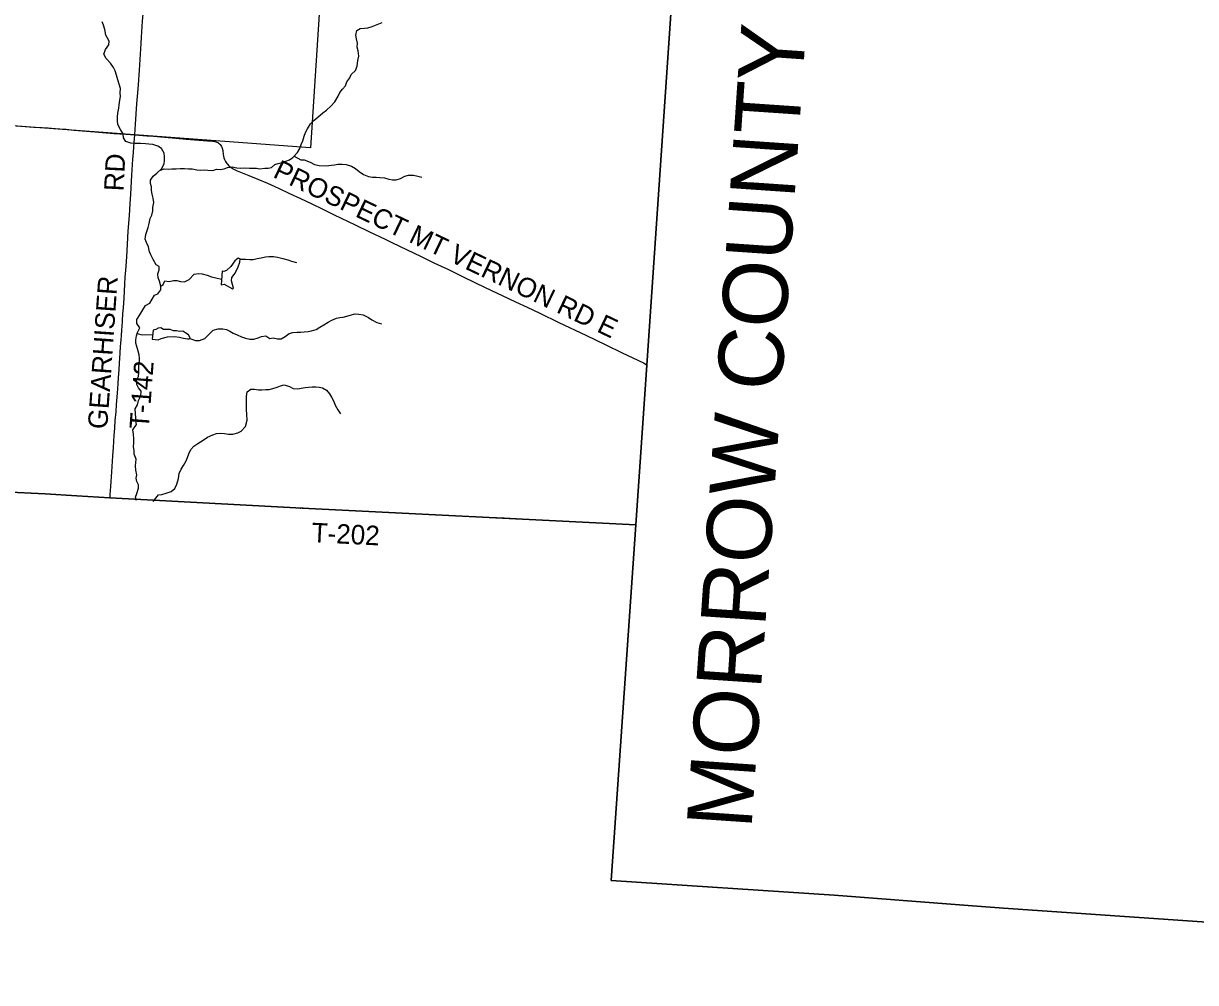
# Model space of a CAD drawing. Extents: x 1584893 to 1934202, y 663575 to 1091909.
# Drawn here: x 1814023 to 1832085, y 879859 to 894636 of the extents above; entities that cross this region are included whole.
import ezdxf

# ---------------------------------------------------------------- set-up
doc = ezdxf.new("R2010")
doc.units = 0
for name, color, linetype in [('GM_X_Adjacent_County', 7, 'Continuous'), ('GM_X_Adjacent_County_Text', 7, 'Continuous'), ('GM_X_County', 7, 'Continuous'), ('GM_X_Minor_Lake', 7, 'Continuous'), ('GM_X_Minor_River', 7, 'Continuous'), ('GM_X_Section', 7, 'Continuous'), ('GM_X_Township', 7, 'Continuous'), ('GM_X_Township_Road', 7, 'Continuous'), ('GM_X_Township_Road_Text', 7, 'Continuous')]:
    doc.layers.add(name, color=color, linetype=linetype)

msp = doc.modelspace()

# ---------------------------------------------------------------- linework, layer by layer
at = {"layer": 'GM_X_Adjacent_County'}
for points in [[(1850147, 879854), (1845959, 880135), (1842150, 880416), (1839410, 880574), (1836708, 880754), (1836682, 880495), (1835395, 880574), (1829123, 881005), (1828513, 881052), (1826517, 881205), (1823082, 881429), (1823458, 886911), (1823627, 889370), (1824025, 895167), (1824431, 901093), (1824723, 905333), (1827503, 905733)], [(1813717, 887422), (1814360, 887388), (1814847, 887358), (1815353, 887328), (1818316, 887169), (1823458, 886911), (1823082, 881429), (1826517, 881205), (1828513, 881052), (1829123, 881005), (1835395, 880574), (1836682, 880495), (1836708, 880754), (1839410, 880574), (1842150, 880416), (1845959, 880135), (1850147, 879854)]]:
    msp.add_lwpolyline(points, dxfattribs=at)
at = {"layer": 'GM_X_County'}
msp.add_lwpolyline([(1827503, 905733), (1824723, 905333), (1824431, 901093), (1824025, 895167), (1823627, 889370), (1823458, 886911), (1818316, 887169), (1815353, 887328), (1814847, 887358), (1814360, 887388), (1813717, 887422)], dxfattribs=at)
at = {"layer": 'GM_X_Minor_Lake'}
for points in [[(1817072, 890611), (1817118, 890622), (1817243, 890548), (1817259, 890558), (1817231, 890671), (1817236, 890721), (1817285, 890791), (1817332, 890886), (1817358, 890960), (1817364, 891010), (1817332, 891021), (1817282, 890979), (1817220, 890890), (1817151, 890829), (1817111, 890813), (1817083, 890820)], [(1817083, 890820), (1817072, 890611)], [(1816009, 889771), (1816097, 889760), (1816147, 889781), (1816244, 889810), (1816350, 889814), (1816426, 889805), (1816492, 889788), (1816550, 889775), (1816578, 889775), (1816594, 889793), (1816565, 889839), (1816527, 889866), (1816478, 889893), (1816430, 889891), (1816383, 889898), (1816333, 889903), (1816282, 889920), (1816231, 889920), (1816183, 889921), (1816142, 889948), (1816097, 889940), (1816063, 889921), (1816021, 889911)], [(1816021, 889911), (1816009, 889771)]]:
    msp.add_lwpolyline(points, dxfattribs=at)
at = {"layer": 'GM_X_Minor_River'}
for points in [[(1815476, 893078), (1815473, 893138), (1815474, 893200), (1815477, 893253), (1815494, 893329), (1815499, 893385), (1815506, 893455), (1815521, 893511), (1815516, 893569), (1815517, 893633), (1815499, 893700), (1815476, 893766), (1815457, 893841), (1815436, 893906), (1815409, 893958), (1815362, 894023), (1815297, 894096), (1815260, 894161), (1815289, 894233), (1815340, 894306), (1815343, 894366), (1815294, 894455), (1815275, 894542), (1815256, 894608), (1815237, 894661)], [(1816133, 892381), (1816136, 892378), (1816190, 892396), (1816258, 892393), (1816312, 892394), (1816378, 892399), (1816439, 892402), (1816503, 892403), (1816569, 892398), (1816625, 892394), (1816695, 892381), (1816759, 892376), (1816809, 892383), (1816865, 892376), (1816941, 892371), (1816996, 892392), (1817054, 892388), (1817114, 892395), (1817165, 892416), (1817241, 892429), (1817313, 892414), (1817373, 892407), (1817437, 892410), (1817507, 892407), (1817562, 892407), (1817614, 892408), (1817666, 892399), (1817742, 892408), (1817792, 892409), (1817844, 892415), (1817897, 892462), (1817950, 892477), (1818010, 892493), (1818068, 892512), (1818123, 892537), (1818173, 892569), (1818247, 892646), (1818280, 892708), (1818305, 892770), (1818326, 892827), (1818349, 892899), (1818372, 892955), (1818399, 893015), (1818448, 893089), (1818497, 893142), (1818558, 893191), (1818639, 893257), (1818694, 893300), (1818759, 893361), (1818824, 893431), (1818873, 893516), (1818898, 893570), (1818941, 893622), (1818988, 893677), (1819007, 893737), (1819052, 893797), (1819073, 893851), (1819140, 893910), (1819167, 893980), (1819174, 894064), (1819191, 894134), (1819180, 894212), (1819165, 894269), (1819170, 894331), (1819155, 894397), (1819144, 894458), (1819161, 894528), (1819214, 894561), (1819280, 894564), (1819332, 894570), (1819399, 894591), (1819473, 894618), (1819552, 894649)], [(1815764, 887284), (1815752, 887336), (1815769, 887394), (1815798, 887478), (1815797, 887528), (1815772, 887578), (1815762, 887629), (1815771, 887681), (1815756, 887755), (1815751, 887823), (1815761, 887924), (1815730, 888000), (1815731, 888053), (1815720, 888117), (1815722, 888171), (1815725, 888237), (1815720, 888308), (1815709, 888374), (1815763, 888456), (1815757, 888514), (1815756, 888564), (1815751, 888624), (1815746, 888697), (1815781, 888760), (1815794, 888828), (1815831, 888900), (1815836, 888972), (1815797, 889023), (1815770, 889074), (1815763, 889134), (1815794, 889198), (1815803, 889254), (1815801, 889304), (1815802, 889360), (1815811, 889426), (1815814, 889480), (1815805, 889531), (1815789, 889585), (1815768, 889660), (1815755, 889712), (1815756, 889764), (1815765, 889822), (1815782, 889876), (1815817, 889948), (1815770, 890015), (1815769, 890077), (1815818, 890145), (1815865, 890222), (1815902, 890290), (1815969, 890325), (1816008, 890387), (1816041, 890451), (1816093, 890472), (1816138, 890530), (1816139, 890590), (1816118, 890664), (1816097, 890717), (1816096, 890779), (1816117, 890841), (1816117, 890891), (1816066, 890918), (1816021, 891001), (1815988, 891070), (1815964, 891120), (1815952, 891193), (1815918, 891261), (1815899, 891314), (1815910, 891384), (1815944, 891492), (1815959, 891552), (1815976, 891630), (1816001, 891684), (1816016, 891748), (1816015, 891802), (1816030, 891876), (1816023, 891942), (1816006, 892005), (1815996, 892063), (1815997, 892117), (1815980, 892168), (1815981, 892224), (1816022, 892286), (1816077, 892331), (1816152, 892398), (1816193, 892472), (1816196, 892524), (1816195, 892588), (1816191, 892638), (1816148, 892711), (1816095, 892746), (1816017, 892769), (1815955, 892778), (1815903, 892783), (1815827, 892786), (1815747, 892787), (1815678, 892792), (1815601, 892819), (1815565, 892872), (1815562, 892936), (1815517, 893003), (1815476, 893078)], [(1818197, 892594), (1818299, 892537), (1818351, 892534), (1818439, 892501), (1818509, 892464), (1818581, 892447), (1818693, 892445), (1818763, 892452), (1818818, 892459), (1818870, 892467), (1818934, 892466), (1818998, 892461), (1819078, 892440), (1819141, 892401), (1819195, 892356), (1819264, 892308), (1819338, 892279), (1819400, 892268), (1819456, 892266), (1819516, 892263), (1819586, 892256), (1819656, 892235), (1819712, 892226), (1819768, 892227), (1819833, 892248), (1819902, 892285), (1819958, 892299), (1820034, 892298), (1820102, 892285), (1820162, 892270)], [(1817364, 891006), (1817443, 891005), (1817511, 891000), (1817565, 891002), (1817627, 891013), (1817687, 891024), (1817754, 891041), (1817804, 891048), (1817878, 891045), (1817936, 891038), (1818022, 891013), (1818098, 890992), (1818156, 890975), (1818232, 890952)], [(1816139, 890590), (1816174, 890614), (1816204, 890669), (1816268, 890660), (1816337, 890675), (1816387, 890675), (1816441, 890658), (1816507, 890655), (1816578, 890692), (1816655, 890771), (1816723, 890786), (1816775, 890778), (1816855, 890757), (1816919, 890734), (1816987, 890717), (1817076, 890697)], [(1816586, 889783), (1816676, 889751), (1816734, 889751), (1816817, 889784), (1816884, 889847), (1816949, 889910), (1817024, 889931), (1817098, 889930), (1817150, 889919), (1817201, 889893), (1817257, 889866), (1817317, 889841), (1817385, 889810), (1817447, 889787), (1817514, 889770), (1817571, 889771), (1817639, 889794), (1817692, 889815), (1817758, 889823), (1817821, 889784), (1817872, 889793), (1817938, 889778), (1817994, 889777), (1818056, 889812), (1818117, 889858), (1818174, 889873), (1818240, 889878), (1818290, 889881), (1818350, 889887), (1818413, 889892), (1818463, 889901), (1818533, 889920), (1818592, 889959), (1818653, 889993), (1818717, 890034), (1818776, 890063), (1818845, 890094), (1818901, 890106), (1818951, 890111), (1819005, 890124), (1819060, 890144), (1819134, 890161), (1819190, 890156), (1819258, 890145), (1819338, 890106), (1819394, 890071), (1819471, 890027), (1819541, 890008)], [(1815776, 889859), (1815853, 889841), (1815903, 889845), (1816015, 889839)], [(1816022, 887269), (1816065, 887321), (1816104, 887373), (1816158, 887380), (1816220, 887399), (1816297, 887424), (1816358, 887472), (1816387, 887538), (1816410, 887627), (1816425, 887704), (1816452, 887767), (1816489, 887827), (1816532, 887895), (1816551, 887947), (1816570, 888007), (1816601, 888070), (1816648, 888124), (1816709, 888165), (1816792, 888218), (1816857, 888260), (1816941, 888298), (1816998, 888318), (1817056, 888325), (1817122, 888318), (1817184, 888307), (1817248, 888308), (1817327, 888327), (1817377, 888353), (1817446, 888426), (1817470, 888522), (1817467, 888616), (1817462, 888681), (1817459, 888751), (1817461, 888887), (1817470, 888959), (1817529, 889001), (1817583, 889002), (1817647, 888993), (1817697, 888990), (1817756, 888994), (1817808, 888999), (1817864, 889012), (1817933, 889035), (1817983, 889053), (1818039, 889066), (1818121, 889041), (1818179, 889012), (1818251, 889007), (1818305, 889018), (1818364, 889027), (1818414, 889035), (1818470, 889038), (1818528, 889037), (1818580, 889034), (1818632, 889023), (1818694, 888988), (1818741, 888932), (1818771, 888879), (1818804, 888812), (1818827, 888754), (1818866, 888685), (1818907, 888620)]]:
    msp.add_lwpolyline(points, dxfattribs=at)
at = {"layer": 'GM_X_Section'}
msp.add_lwpolyline([(1818797, 898114), (1818447, 892718), (1813023, 893121), (1813386, 898492)], close=True, dxfattribs=at)
at = {"layer": 'GM_X_Township'}
msp.add_lwpolyline([(1809793, 903371), (1814408, 903992), (1817717, 904437), (1822057, 905021), (1822465, 905074), (1824723, 905333), (1824431, 901093), (1824025, 895167), (1823627, 889370), (1823458, 886911), (1818316, 887169), (1815353, 887328), (1814847, 887358), (1814360, 887388), (1813717, 887422)], dxfattribs=at)
at = {"layer": 'GM_X_Township_Road'}
for points in [[(1815737, 892920), (1815738, 892922), (1815750, 893085), (1815772, 893396), (1815781, 893510), (1815794, 893690), (1815810, 893919), (1815832, 894246), (1815837, 894327), (1815844, 894426), (1815855, 894589), (1815860, 894671), (1815868, 894785), (1815878, 894920), (1815885, 895032), (1815891, 895120), (1815896, 895210), (1815903, 895325), (1815918, 895488), (1815924, 895570), (1815926, 895600)], [(1813011, 893120), (1813247, 893104), (1813657, 893075), (1813837, 893063), (1813984, 893052), (1814181, 893040), (1814311, 893031), (1814375, 893027), (1814404, 893027), (1814454, 893023), (1814585, 893015), (1814683, 893006), (1814797, 892993), (1815124, 892966), (1815418, 892943), (1815599, 892930), (1815737, 892920)], [(1815357, 887331), (1815361, 887377), (1815371, 887501), (1815387, 887730), (1815402, 887975), (1815411, 888105), (1815421, 888286), (1815430, 888399), (1815439, 888517), (1815450, 888653), (1815459, 888767), (1815462, 888823), (1815471, 888938), (1815482, 889086), (1815489, 889182), (1815497, 889299), (1815504, 889407), (1815508, 889473), (1815521, 889653), (1815529, 889767), (1815533, 889816), (1815535, 889848), (1815536, 889863), (1815538, 889878), (1815539, 889891), (1815541, 889919), (1815544, 889964), (1815550, 890056), (1815557, 890163), (1815563, 890257), (1815573, 890404), (1815586, 890617), (1815593, 890731), (1815600, 890829), (1815614, 891041), (1815625, 891238), (1815639, 891434), (1815655, 891679), (1815667, 891859), (1815677, 892006), (1815694, 892301), (1815709, 892546), (1815717, 892644), (1815724, 892742), (1815737, 892920)], [(1815737, 892920), (1815926, 892906), (1816029, 892898), (1816139, 892890), (1816252, 892881), (1816369, 892870), (1816530, 892856), (1816661, 892843), (1816857, 892828), (1816938, 892821), (1816971, 892816), (1816987, 892812), (1817002, 892807), (1817017, 892800), (1817031, 892792), (1817044, 892781), (1817056, 892770), (1817066, 892757), (1817074, 892743), (1817082, 892728), (1817087, 892713), (1817094, 892681), (1817103, 892616), (1817106, 892593), (1817113, 892565), (1817123, 892539), (1817136, 892511), (1817158, 892481), (1817169, 892466), (1817189, 892445), (1817204, 892432), (1817217, 892422), (1817244, 892404), (1817273, 892388), (1817318, 892368), (1817494, 892295), (1817635, 892236), (1817786, 892174), (1817898, 892123), (1817966, 892091), (1818115, 892021), (1818293, 891938), (1818456, 891860), (1818648, 891768), (1818811, 891689), (1819136, 891533), (1819358, 891427), (1819595, 891314), (1819698, 891263), (1819935, 891149), (1820142, 891049), (1820349, 890949), (1820571, 890843), (1820778, 890744), (1820999, 890637), (1821237, 890524), (1821400, 890446), (1821607, 890347), (1821785, 890263), (1821978, 890173), (1822274, 890031), (1822689, 889833), (1823000, 889683), (1823251, 889561), (1823576, 889405), (1823621, 889383), (1823631, 889378)], [(1818280, 887162), (1818283, 887165), (1818289, 887169), (1818299, 887170), (1818316, 887171), (1818334, 887171), (1818481, 887161), (1819006, 887135), (1819514, 887112), (1819744, 887102), (1820121, 887082), (1820432, 887068), (1820842, 887046), (1821432, 887018), (1822088, 886984), (1822989, 886935), (1823461, 886911)]]:
    msp.add_lwpolyline(points, dxfattribs=at)

# ---------------------------------------------------------------- texts
at = {"layer": 'GM_X_Adjacent_County_Text'}
msp.add_text('MORROW COUNTY', height=1000, rotation=86.0901, dxfattribs=at).set_placement((1825240, 882214))
at = {"layer": 'GM_X_Township_Road_Text'}
for s, rotation, p in [('RD', 87.0131, (1815564, 892046)), ('PROSPECT MT VERNON RD E', 334.5087, (1817853, 892274)), ('GEARHISER', 86.0007, (1815313, 888379)), ('T-142', 85.8354, (1815955, 888381)), ('T-202', 357.195, (1818459, 886645))]:
    msp.add_text(s, height=300, rotation=rotation, dxfattribs=at).set_placement(p)

doc.saveas('drawing.dxf')
